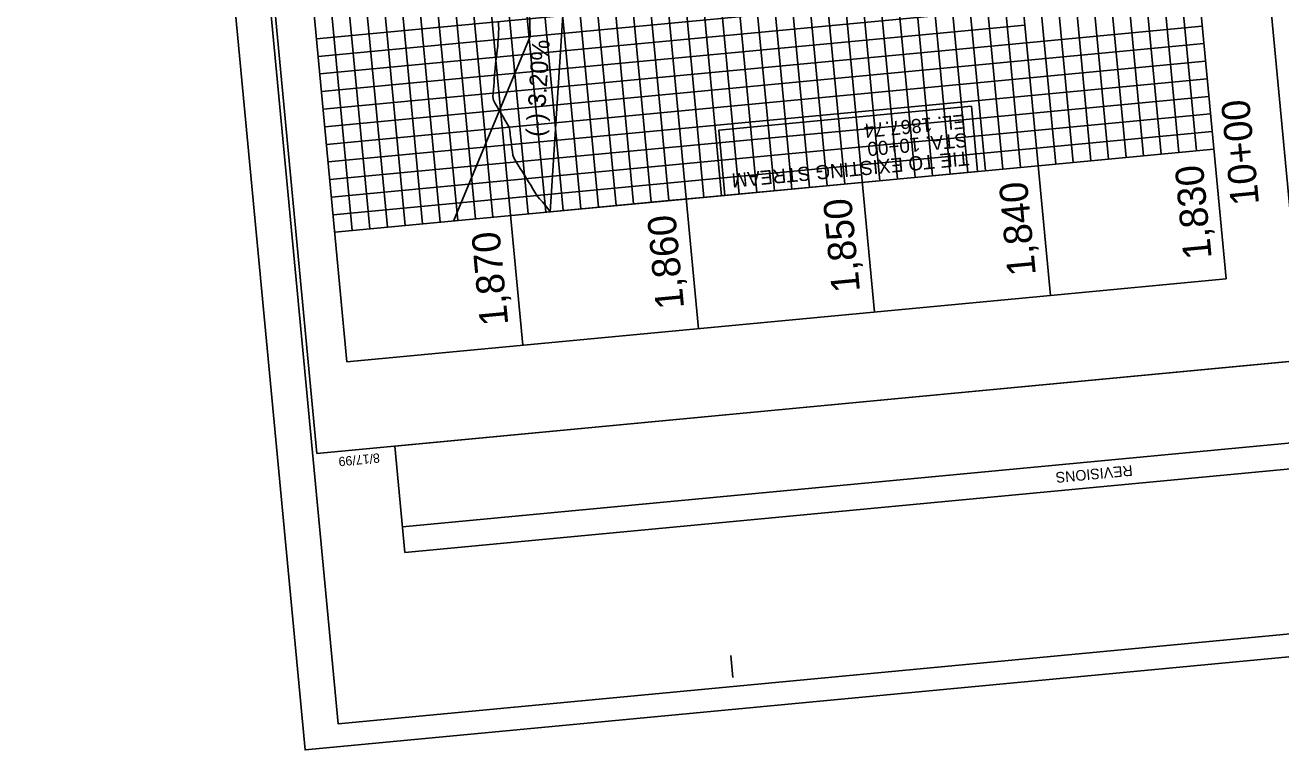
# Model space of a CAD drawing. Extents: x 554635 to 555260, y 497951 to 498841.
# Drawn here: x 554635.2 to 554990.7, y 497951 to 498156.2 of the extents above; entities that cross this region are included whole.
import ezdxf

# ---------------------------------------------------------------- set-up
doc = ezdxf.new("R2010")
doc.units = 0
for name, color, linetype in [('Exist Vertical Profile Ground Line', 7, 'Continuous'), ('Exist Vertical Profile Horizontal Axis Label Major', 7, 'Continuous'), ('Exist Vertical Profile Vertical Axis Label', 7, 'Continuous'), ('Prop Drainage Ditch Boundaries', 7, 'Continuous'), ('Prop Plan Preparation Sheet Bridge Report Non FEMA CELL', 7, 'Continuous'), ('Prop Vertical Profile Ditch Grade Median', 7, 'Continuous'), ('Prop Vertical Profile Ditch Grade Median Label', 7, 'Continuous'), ('Prop VPI Ditch Grade Median Label', 7, 'Continuous'), ('Prop VPT Ditch Grade Median Label', 7, 'Continuous'), ('Sheet Block Revision CELL', 7, 'Continuous'), ('Sheet Layout Plan Border', 7, 'Continuous'), ('Sheet Plan CELL', 7, 'Continuous'), ('Sheet Plot Border Inside CELL', 7, 'Continuous'), ('Sheet Plot Border Outside CELL', 7, 'Continuous')]:
    doc.layers.add(name, color=color, linetype=linetype)

msp = doc.modelspace()

# ---------------------------------------------------------------- linework, layer by layer
at = {"layer": 'Exist Vertical Profile Ground Line'}
msp.add_lwpolyline([(554783.88, 498103.34), (554783.18, 498104.28), (554782.44, 498105.22), (554781.66, 498106.15), (554780.87, 498107.08), (554780.09, 498108.01), (554779.51, 498108.96), (554778.92, 498109.91), (554778.34, 498110.86), (554777.75, 498111.81), (554777.17, 498112.75), (554776.58, 498113.7), (554776, 498114.65), (554775.41, 498115.6), (554774.83, 498116.55), (554774.25, 498117.5), (554773.66, 498118.45), (554773.32, 498119.42), (554773.19, 498120.41), (554773.05, 498121.41), (554772.92, 498122.4), (554772.78, 498123.39), (554772.65, 498124.38), (554772.51, 498125.37), (554772.47, 498126.37), (554772.26, 498127.36), (554771.69, 498128.31), (554771.13, 498129.26), (554770.56, 498130.21), (554769.99, 498131.16), (554769.43, 498132.11), (554768.86, 498133.06), (554768.32, 498134.02), (554767.8, 498134.97), (554767.65, 498135.96), (554767.73, 498136.97), (554767.8, 498137.99), (554767.88, 498139), (554767.96, 498140.01), (554768.03, 498141.02), (554768.11, 498142.03), (554768.18, 498143.04), (554768.26, 498144.06), (554768.39, 498145.07), (554768.51, 498146.09), (554768.63, 498147.1), (554768.76, 498148.12), (554768.88, 498149.14), (554769.01, 498150.15), (554769.09, 498151.16), (554769.15, 498152.17), (554769.21, 498153.18), (554769.26, 498154.19), (554769.3, 498155.2), (554769.26, 498156.2), (554769.22, 498157.2)], dxfattribs=at)
at = {"layer": 'Prop Drainage Ditch Boundaries'}
msp.add_lwpolyline([(554756.46, 498100.75), (554778.24, 498153.03), (554776.77, 498203.12), (554782.76, 498253.91), (554787.47, 498304.58), (554794.13, 498350.41)], dxfattribs=at)
at = {"layer": 'Prop Plan Preparation Sheet Bridge Report Non FEMA CELL'}
for p, q in [((554975.22, 498084.39), (554938.81, 498469.55)), ((554892.11, 498113.58), (554859.16, 498462.02)), ((554897.09, 498114.05), (554864.14, 498462.49)), ((554902.06, 498114.52), (554869.12, 498462.96)), ((554907.04, 498114.99), (554874.1, 498463.43)), ((554912.02, 498115.46), (554879.08, 498463.9)), ((554917, 498115.93), (554884.05, 498464.38)), ((554925.45, 498079.69), (554889.03, 498464.85)), ((554925.45, 498079.69), (554889.03, 498464.85)), ((554926.95, 498116.87), (554894.01, 498465.32)), ((554857.26, 498110.28), (554824.32, 498458.73)), ((554862.24, 498110.75), (554829.3, 498459.2)), ((554867.22, 498111.22), (554834.28, 498459.67)), ((554875.67, 498074.98), (554839.25, 498460.14)), ((554877.17, 498112.16), (554844.23, 498460.61)), ((554882.15, 498112.64), (554849.21, 498461.08)), ((554887.13, 498113.11), (554854.19, 498461.55)), ((554817.44, 498106.52), (554784.5, 498454.96)), ((554825.89, 498070.27), (554789.48, 498455.43)), ((554827.4, 498107.46), (554794.45, 498455.9)), ((554832.37, 498107.93), (554799.43, 498456.38)), ((554837.35, 498108.4), (554804.41, 498456.85)), ((554842.33, 498108.87), (554809.39, 498457.32)), ((554847.31, 498109.34), (554814.36, 498457.79)), ((554852.29, 498109.81), (554819.34, 498458.26)), ((554777.62, 498102.75), (554744.68, 498451.2)), ((554782.6, 498103.22), (554749.65, 498451.67)), ((554787.57, 498103.69), (554754.63, 498452.14)), ((554792.55, 498104.16), (554759.61, 498452.61)), ((554797.53, 498104.63), (554764.59, 498453.08)), ((554802.51, 498105.11), (554769.56, 498453.55)), ((554807.48, 498105.58), (554774.54, 498454.02)), ((554812.46, 498106.05), (554779.52, 498454.49)), ((554742.77, 498099.46), (554709.83, 498447.9)), ((554747.75, 498099.93), (554714.81, 498448.37)), ((554752.73, 498100.4), (554719.79, 498448.85)), ((554757.71, 498100.87), (554724.76, 498449.32)), ((554762.68, 498101.34), (554729.74, 498449.79)), ((554767.66, 498101.81), (554734.72, 498450.26)), ((554776.11, 498065.57), (554739.7, 498450.73)), ((554726.33, 498060.86), (554689.92, 498446.02)), ((554727.84, 498098.05), (554694.9, 498446.49)), ((554732.82, 498098.52), (554699.87, 498446.96)), ((554737.8, 498098.99), (554704.85, 498447.43)), ((554946.86, 498118.75), (554921.8, 498383.85)), ((554951.84, 498119.22), (554926.78, 498384.32)), ((554956.82, 498119.69), (554931.76, 498384.79)), ((554961.8, 498120.16), (554936.73, 498385.26)), ((554966.77, 498120.64), (554941.71, 498385.73)), ((554931.93, 498117.34), (554906.87, 498382.44)), ((554936.91, 498117.81), (554911.84, 498382.91)), ((554941.89, 498118.28), (554916.82, 498383.38)), ((554916.8, 498171.16), (554717.69, 498152.33)), ((554917.27, 498166.18), (554718.16, 498147.35)), ((554917.74, 498161.2), (554718.63, 498142.38)), ((554918.21, 498156.22), (554719.1, 498137.4)), ((554968.46, 498155.95), (554918.68, 498151.24)), ((554918.68, 498151.24), (554719.57, 498132.42)), ((554968.93, 498150.97), (554919.15, 498146.27)), ((554919.15, 498146.27), (554720.04, 498127.44)), ((554969.4, 498146), (554919.62, 498141.29)), ((554919.62, 498141.29), (554720.51, 498122.46)), ((554969.87, 498141.02), (554920.09, 498136.31)), ((554920.09, 498136.31), (554720.98, 498117.49)), ((554970.34, 498136.04), (554920.56, 498131.33)), ((554920.56, 498131.33), (554721.45, 498112.51)), ((554970.81, 498131.06), (554921.03, 498126.36)), ((554921.03, 498126.36), (554721.92, 498107.53)), ((554971.28, 498126.08), (554921.5, 498121.38)), ((554921.5, 498121.38), (554722.39, 498102.55)), ((554971.75, 498121.11), (554921.97, 498116.4)), ((554921.97, 498116.4), (554722.86, 498097.58)), ((554975.22, 498084.39), (554925.45, 498079.69)), ((554925.45, 498079.69), (554726.33, 498060.86))]:
    msp.add_line(p, q, dxfattribs=at)
at = {"layer": 'Prop Vertical Profile Ditch Grade Median'}
msp.add_lwpolyline([(554783.89, 498103.35), (554787.86, 498164.99), (554792.83, 498165.46), (554791.89, 498175.42), (554788.62, 498177.12), (554791.82, 498226.64), (554796.8, 498227.11), (554795.86, 498237.07), (554792.63, 498238.77), (554795.79, 498288.29), (554800.76, 498288.76), (554799.82, 498298.71), (554796.6, 498300.42), (554799.85, 498350.97)], dxfattribs=at)
at = {"layer": 'Prop VPT Ditch Grade Median Label'}
for points in [[(554833.34, 498108.02), (554831.6, 498126.5), (554903.09, 498133.26), (554904.83, 498114.78)], [(554833.34, 498108.02), (554817.44, 498106.52), (554783.89, 498103.35), (554783.89, 498103.35)]]:
    msp.add_lwpolyline(points, close=True, dxfattribs=at)
msp.add_lwpolyline([(554904.83, 498114.78), (554903.09, 498133.26), (554831.6, 498126.5), (554833.34, 498108.02), (554904.83, 498114.78)], dxfattribs=at)
at = {"layer": 'Sheet Block Revision CELL'}
msp.add_line((555135.63, 498051.36), (554742.07, 498014.14), dxfattribs=at)
msp.add_lwpolyline([(555136.33, 498044.11), (554742.76, 498006.91), (554739.9, 498037.04), (555133.47, 498074.25)], close=True, dxfattribs=at)
at = {"layer": 'Sheet Layout Plan Border'}
msp.add_lwpolyline([(555232.94, 498108.76), (555192.39, 498537.63), (554954.42, 498515.13), (554994.97, 498086.26)], close=True, dxfattribs=at)
msp.add_lwpolyline([(555232.94, 498108.76), (555192.39, 498537.63), (554954.42, 498515.13), (554994.97, 498086.26)], close=True, dxfattribs=at)
at = {"layer": 'Sheet Plan CELL'}
msp.add_line((554835.58, 497971.5), (554834.98, 497977.72), dxfattribs=at)
msp.add_lwpolyline([(554647.23, 498781.63), (554717.82, 498034.95), (555240.49, 498084.36), (555169.9, 498831.04)], close=True, dxfattribs=at)
at = {"layer": 'Sheet Plot Border Inside CELL'}
msp.add_lwpolyline([(555248.96, 498008.08), (555170.55, 498837.37), (554645.4, 498787.73), (554723.81, 497958.43)], close=True, dxfattribs=at)
at = {"layer": 'Sheet Plot Border Outside CELL'}
msp.add_lwpolyline([(555259.53, 498002.55), (555180.3, 498840.56), (554635.23, 498789.03), (554714.46, 497951.01)], close=True, dxfattribs=at)

# ---------------------------------------------------------------- texts
at = {"layer": 'Exist Vertical Profile Horizontal Axis Label Major'}
msp.add_text('10+00', height=8, rotation=95.4008, dxfattribs=at).set_placement((554984.53, 498105.54))
at = {"layer": 'Exist Vertical Profile Vertical Axis Label'}
for s, p in [('1,830', (554971.13, 498090.26)), ('1,840', (554921.35, 498085.56)), ('1,850', (554871.57, 498080.85)), ('1,860', (554821.79, 498076.15)), ('1,870', (554772.02, 498071.44))]:
    msp.add_text(s, height=8, rotation=95.4008, dxfattribs=at).set_placement(p)
at = {"layer": 'Prop Vertical Profile Ditch Grade Median Label'}
msp.add_text('(-) 3.20%', height=5, rotation=86.2991, dxfattribs=at).set_placement((554782, 498124.5))
at = {"layer": 'Prop VPI Ditch Grade Median Label'}
for s, p in [('EL. 1867.74', (554901.25, 498130.96)), ('STA. 10+00 ', (554901.74, 498125.74)), ('TIE TO EXISTING STREAM', (554902.24, 498120.52))]:
    msp.add_text(s, height=4, rotation=185.4008, dxfattribs=at).set_placement(p)
at = {"layer": 'Sheet Block Revision CELL'}
msp.add_text('REVISIONS', height=3, rotation=185.4008, dxfattribs=at).set_placement((554948.58, 498031.64))
at = {"layer": 'Sheet Plan CELL'}
msp.add_text('8/17/99', height=2.625, rotation=185.4008, dxfattribs=at).set_placement((554735.51, 498035))

doc.saveas('drawing.dxf')
